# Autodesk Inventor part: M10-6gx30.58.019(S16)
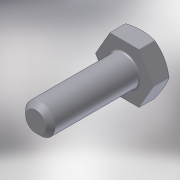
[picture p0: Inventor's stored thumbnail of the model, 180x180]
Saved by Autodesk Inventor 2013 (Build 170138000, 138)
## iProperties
Shininess: 20.0
Length Units: 11269
Angle Units: 11279
Time Units: 11290
Mass Units: 11283
Length Display Precision: 3
Angle Display Precision: 2
Created: 2001-10
Document SubType Name: Modeling
Designer: SaAlex
Description: Болт M10-6gx30.58.019 (S16) ГОСТ 7798-70
Material: Steel, Mild
Mass: 30.6674 g
Surface Area: 17.5054 cm^2
Volume: 3.9017 cm^3
Density: 7.86 g/cm^3
Density: 0.0
Volumn: 0.0
Area: 0.0
PropertySet Name: Model Information
Control State: 0
Master: False
Checked Out: False
Checked Out Date: 2008-10-15
Last Check In Date: 2008-10-15
Author: SaAlex
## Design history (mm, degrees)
sketch "Sketch1"
  geometry: L1 (484.39, 469.325)-(474.575, 469.325); L2 (489.297, 460.825)-(484.39, 469.325); L3 (484.39, 452.325)-(489.297, 460.825); L4 (474.575, 452.325)-(484.39, 452.325); L5 (469.667, 460.825)-(474.575, 452.325); L6 (474.575, 469.325)-(469.667, 460.825); C1 r 8.5 at (479.482, 460.825)
  constraints: 12 end point, 6 tangent, 3 parallel, 1 centre point, 1 horizontal, 1 other
  dimensions: "d1" = 120 deg angle of L1 L2; "d3" = 120 deg angle of L5 L6; "d5" = 17 diameter of C1
extrude "ExtrusionBlind1" new body sketch "Sketch1" distance "d6" = 6.4; taper "d7" = 0 deg
sketch "Sketch2"
  geometry: C1 r 7.8 at (479.482, -460.825)
  constraints: 1 centre point
  dimensions: "d12" = 15.6 diameter of C1
extrude "ExtrusionThru1" sketch "Sketch2" stored distance "d13" = 0.13; taper "d14" = 60 deg
sketch "Sketch3"
  geometry: L1 (469.667, 460.825)-(470.167, 461.691); L2 (474.575, 469.325)-(475.575, 469.325); L3 (484.39, 469.325)-(484.89, 468.459); C1 r 5 at (479.482, 460.825); C2 r 8.5 at (479.482, 460.825)
  constraints: 6 end point, 3 tangent, 2 centre point, 1 coincident
  dimensions: "d16" = 10 diameter of C1
extrude "ExtrusionBlind2" join sketch "Sketch3" distance "d17" = 30; taper "d18" = 0 deg
fillet "Fillet1" dims "d19" = 0.5
chamfer "Chamfer1" distance "d20" = 1.6; stored, may be unused: second distance "d21" = 1.6, angle "d22" = 45 deg
body "Solid1"
other parameters: "d0" = 120 deg (derived), "d2" = 120 deg (derived), "d4" = 17 (derived), "d8" = 0, "d9" = 0, "d10" = 0, "d11" = 15.6 (derived), "d23" = 0
